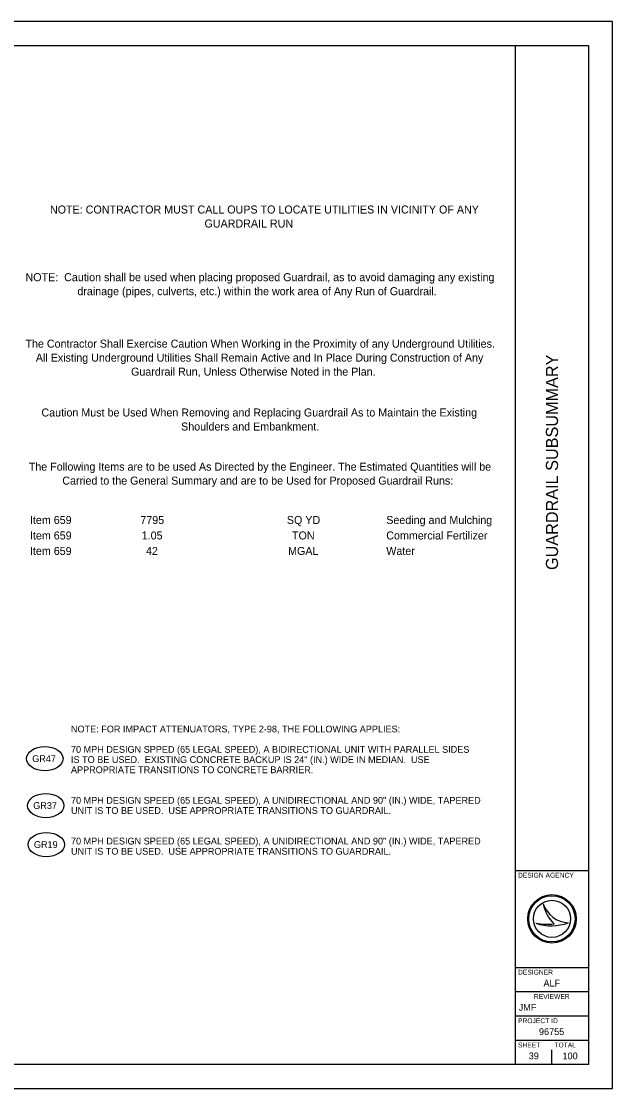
# Model space of a CAD drawing. Extents: x 0 to 34, y 0 to 22.
# Drawn here: x 21.82 to 34, y 0 to 22 of the extents above; entities that cross this region are included whole.
import ezdxf

# ---------------------------------------------------------------- set-up
doc = ezdxf.new("R2010")
doc.units = 0
for name, color, linetype in [('Default', 7, 'Continuous'), ('SH_Border', 7, 'Continuous'), ('SH_Cut_Line', 7, 'Continuous'), ('SH_Data', 7, 'Continuous')]:
    doc.layers.add(name, color=color, linetype=linetype)

msp = doc.modelspace()

# ---------------------------------------------------------------- linework, layer by layer
at = {"layer": 'Default'}
for centre in [(22.301, 6.802), (22.321, 5.835), (22.331, 5.031)]:
    msp.add_ellipse(centre, major_axis=(0.375, 0), ratio=0.666667, dxfattribs=at)
at = {"layer": 'SH_Border'}
for p, q in [((32, 0.5), (32, 21.5)), ((32, 4.5), (33.5, 4.5)), ((32, 2.5), (33.5, 2.5)), ((32, 2), (33.5, 2)), ((32, 1.5), (33.5, 1.5)), ((32, 1), (33.5, 1))]:
    msp.add_line(p, q, dxfattribs=at)
msp.add_lwpolyline([(1.5, 21.5), (33.5, 21.5), (33.5, 0.5), (1.5, 0.5)], close=True, dxfattribs=at)
at = {"layer": 'SH_Cut_Line'}
msp.add_lwpolyline([(0, 0), (34, 0), (34, 22), (0, 22)], close=True, dxfattribs=at)
at = {"layer": 'SH_Data'}
for p, q in [((32.567, 3.81), (32.567, 3.81)), ((32.417, 3.41), (32.417, 3.41)), ((32.75, 3.5), (32.75, 3.5)), ((33.087, 3.419), (33.087, 3.419)), ((32.375, 0.675), (32.375, 0.675)), ((32.75, 0.5), (32.75, 0.8))]:
    msp.add_line(p, q, dxfattribs=at)
for radius in [0.5, 0.477, 0.477, 0.382]:
    msp.add_circle((32.75, 3.5), radius, dxfattribs=at)
for centre, radius, start, end in [((33.116, 3.998), 0.58, 198.9257, 198.9319), ((33.347, 3.97), 0.796, 191.6379, 191.6421), ((33.116, 3.998), 0.58, 198.9319, 267.1657), ((33.347, 3.97), 0.796, 191.6421, 226.0947), ((32.739, 4.37), 1.013, 251.4576, 290.0832), ((32.648, 4.654), 1.266, 259.4964, 259.4995), ((32.739, 4.37), 1.013, 251.4527, 251.4576), ((32.648, 4.654), 1.266, 259.4995, 276.6672)]:
    msp.add_arc(centre, radius, start, end, dxfattribs=at)

# ---------------------------------------------------------------- texts
at = {"layer": 'Default'}
for s, height, p in [('   NOTE: CONTRACTOR MUST CALL OUPS TO LOCATE UTILITIES IN VICINITY OF ANY ', 0.16495, (22.224, 18.039)), ('GUARDRAIL RUN', 0.16495, (25.591, 17.75)), ('NOTE:  Caution shall be used when placing proposed Guardrail, as to avoid damaging any existing ', 0.16495, (21.903, 16.644)), ('drainage (pipes, culverts, etc.) within the work area of Any Run of Guardrail.', 0.16495, (22.972, 16.355)), ('The Contractor Shall Exercise Caution When Working in the Proximity of any Underground Utilities. ', 0.16495, (21.902, 15.274)), ('All Existing Underground Utilities Shall Remain Active and In Place During Construction of Any ', 0.16495, (22.116, 14.986)), ('Guardrail Run, Unless Otherwise Noted in the Plan.', 0.16495, (24.078, 14.697)), ('Caution Must be Used When Removing and Replacing Guardrail As to Maintain the Existing ', 0.16495, (22.232, 13.855)), ('Shoulders and Embankment.', 0.16495, (25.109, 13.566)), ('The Following Items are to be used As Directed by the Engineer. The Estimated Quantities will be ', 0.16495, (21.97, 12.739)), ('Carried to the General Summary and are to be Used for Proposed Guardrail Runs:', 0.16495, (22.661, 12.451)), ('Item 659', 0.165, (21.995, 11.639)), ('7795', 0.165, (24.269, 11.639)), ('SQ YD', 0.165, (27.288, 11.639)), ('Seeding and Mulching', 0.16495, (29.336, 11.639)), ('Item 659', 0.165, (21.995, 11.32)), ('1.05', 0.165, (24.298, 11.32)), ('TON', 0.165, (27.394, 11.32)), ('Commercial Fertilizer', 0.16495, (29.336, 11.32)), ('Item 659', 0.165, (21.995, 11.001)), ('42', 0.165, (24.385, 11.001)), ('MGAL', 0.165, (27.313, 11.001)), ('Water', 0.165, (29.336, 11.001)), ('NOTE: FOR IMPACT ATTENUATORS, TYPE 2-98, THE FOLLOWING APPLIES:', 0.14, (22.84, 7.343)), ('70 MPH DESIGN SPPED (65 LEGAL SPEED), A BIDIRECTIONAL UNIT WITH PARALLEL SIDES', 0.14, (22.84, 6.923)), ('GR47', 0.14, (22.041, 6.732)), ('IS TO BE USED.  EXISTING CONCRETE BACKUP IS 24" (IN.) WIDE IN MEDIAN.  USE ', 0.14, (22.84, 6.713)), ('APPROPRIATE TRANSITIONS TO CONCRETE BARRIER.', 0.14, (22.84, 6.503)), ('70 MPH DESIGN SPEED (65 LEGAL SPEED), A UNIDIRECTIONAL AND 90" (IN.) WIDE, TAPERED', 0.14, (22.84, 5.873)), ('GR37', 0.14, (22.062, 5.765)), ('UNIT IS TO BE USED.  USE APPROPRIATE TRANSITIONS TO GUARDRAIL.', 0.14, (22.84, 5.663)), ('GR19', 0.14, (22.076, 4.961)), ('70 MPH DESIGN SPEED (65 LEGAL SPEED), A UNIDIRECTIONAL AND 90" (IN.) WIDE, TAPERED', 0.14, (22.84, 5.033)), ('UNIT IS TO BE USED.  USE APPROPRIATE TRANSITIONS TO GUARDRAIL.', 0.14, (22.84, 4.823))]:
    msp.add_text(s, height=height, dxfattribs=at).set_placement(p)
at = {"layer": 'SH_Data'}
msp.add_text('GUARDRAIL SUBSUMMARY', height=0.25, rotation=90, dxfattribs=at).set_placement((32.875, 10.691))
for s, height, p in [('DESIGN AGENCY', 0.1, (32.05, 4.35)), ('DESIGNER', 0.1, (32.05, 2.35)), ('ALF', 0.14, (32.575, 2.105)), ('REVIEWER', 0.1, (32.378, 1.85)), ('JMF', 0.14, (32.064, 1.605)), ('PROJECT ID', 0.1, (32.05, 1.35)), ('96755', 0.14, (32.482, 1.105)), ('SHEET', 0.1, (32.05, 0.85)), ('TOTAL', 0.1, (32.8, 0.85)), ('39', 0.14, (32.271, 0.605)), ('100', 0.14, (32.967, 0.605))]:
    msp.add_text(s, height=height, dxfattribs=at).set_placement(p)

doc.saveas('drawing.dxf')
